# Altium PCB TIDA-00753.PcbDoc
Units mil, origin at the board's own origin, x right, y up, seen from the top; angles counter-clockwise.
Board outline 3149.61 x 1968.5 mil, 2 copper layers (Top Layer, Bottom Layer), stack 62 mil thick; 92 components, 41 nets, 183 pads, 103 vias.
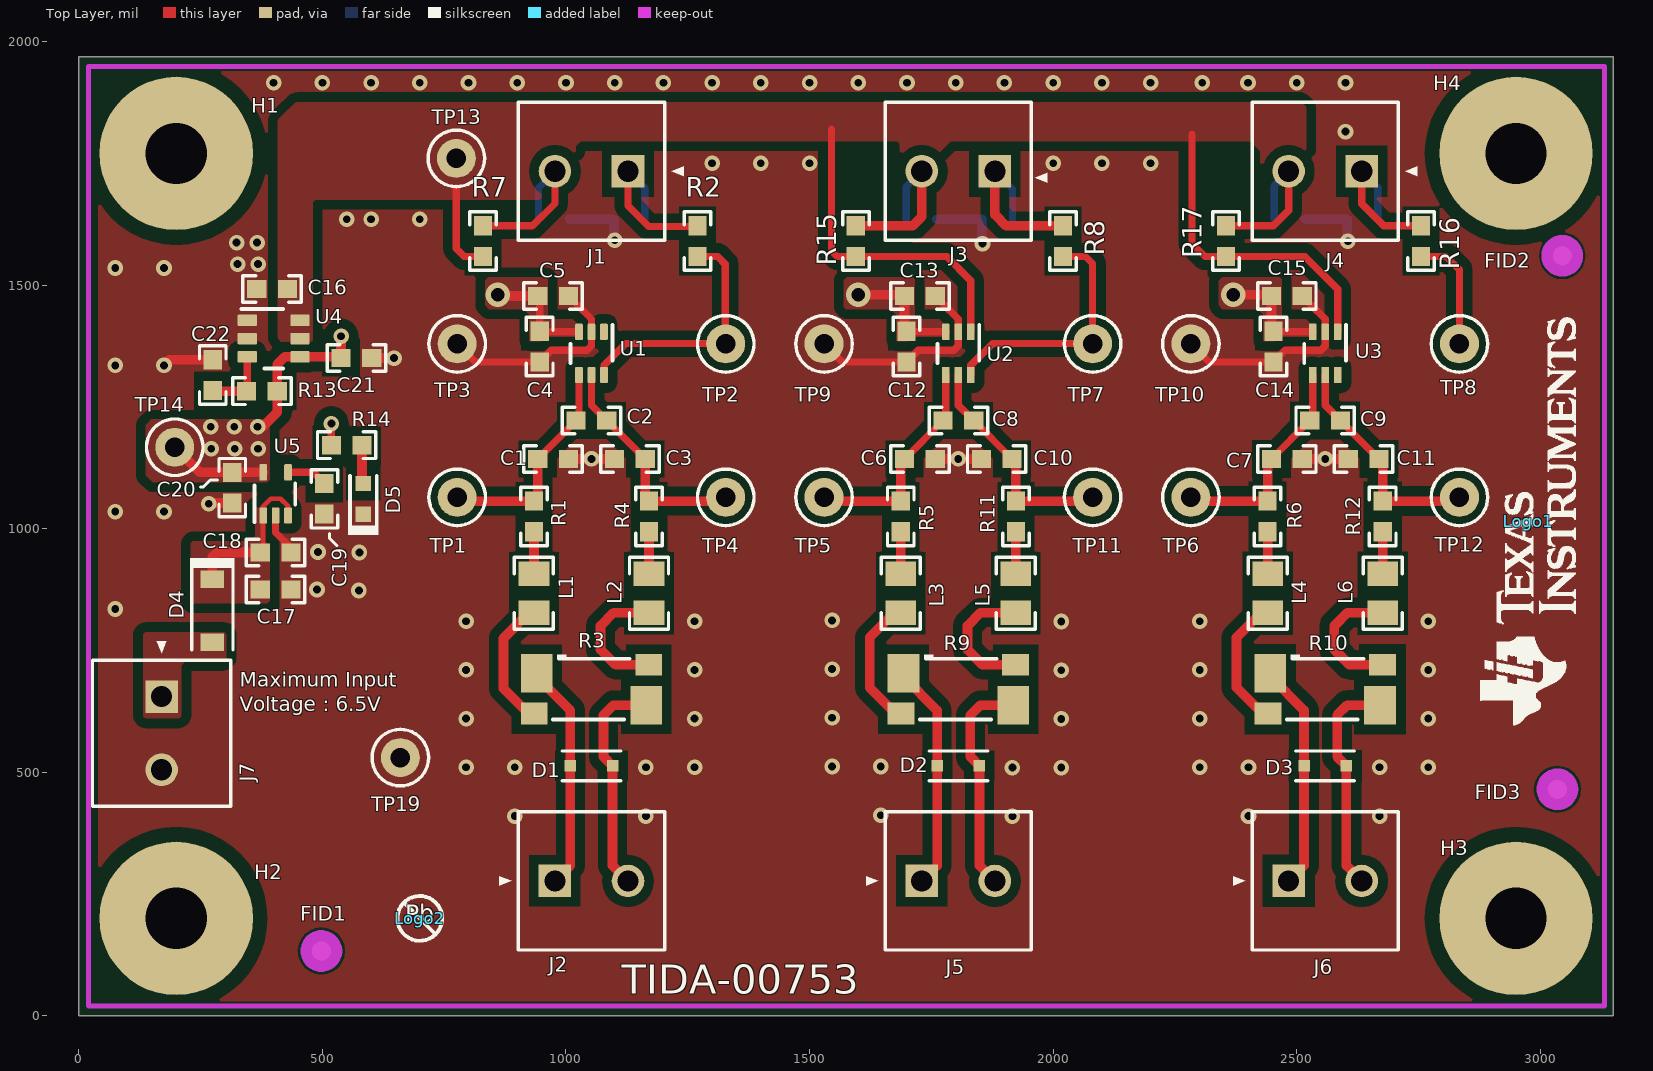
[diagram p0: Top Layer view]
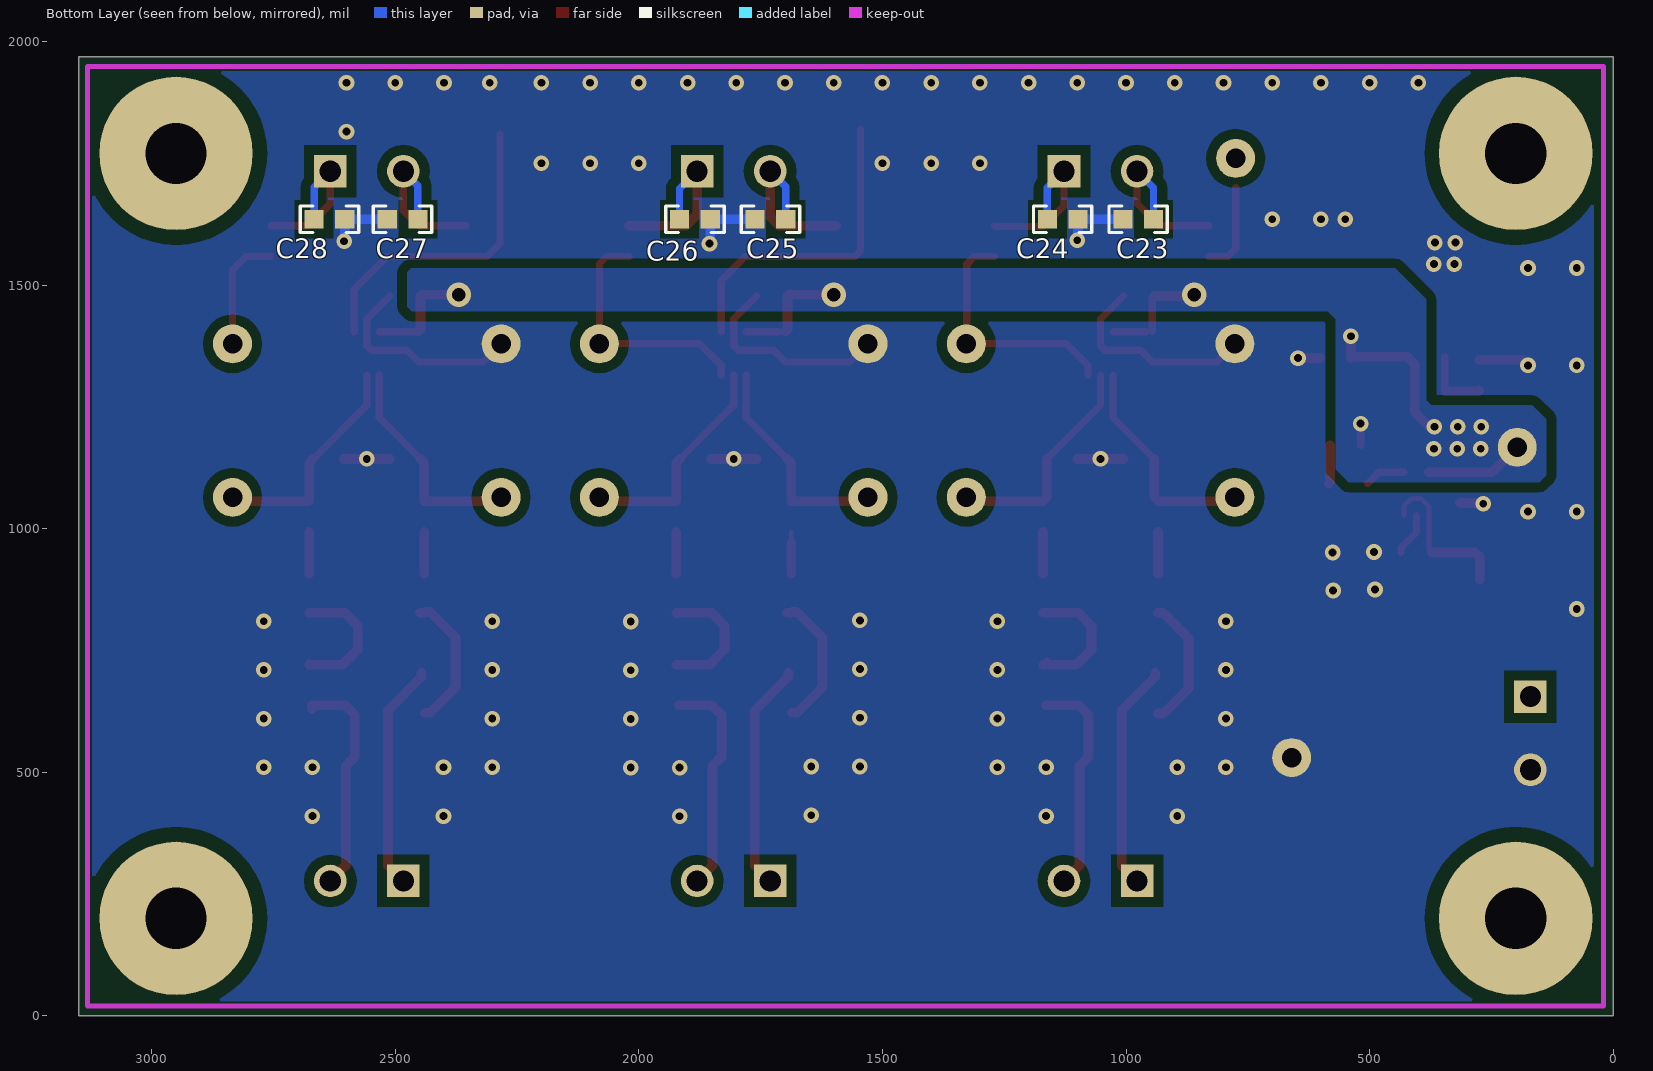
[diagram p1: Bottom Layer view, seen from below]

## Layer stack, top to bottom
Top Solder: solder mask 0.4, Solder Resist, Dk 3.5
Top Layer: signal copper 1.4
Dielectric1: core 59.2, FR-4, Dk 4.8
Bottom Layer: signal copper 1.4
Bottom Solder: solder mask 0.4, Solder Resist, Dk 3.5

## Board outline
0,0 0,1968.5 3149.61,1968.5 3149.61,0

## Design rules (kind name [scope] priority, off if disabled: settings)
AcuteAngle [All] p1: minimum=4.50000000000000E+0001 checktracksonly=FALSE
AssemblyTestPointUsage [All] p1: valid=2
Clearance Clearance_keepout [InPolygon vs IsKeepOut] p1: gap=5
Clearance Clearance_BoardEdge_MountingHoles [OnCopper and InComponentClass('Mounting Holes') vs IsKeepOut] p2: gap=10
Clearance Clearance_HOLES [InPadClass('holes') vs InPoly] p3: gap=30
Clearance "Clearance_Poly to Poly" [InPolygon vs InPolygon] p4: gap=20
Clearance Clearance_Poly [InPolygon] p5: gap=20
Clearance "Clearance_VIA TO VIA" [IsVia vs IsVia] p6: gap=8
Clearance "Clearance_Via to SMD" [IsVia vs IsPad] p7: gap=8
Clearance [All] p8: gap=8
ComponentClearance ComponentClearance_Logo [InComponentClass('Logo')] p1: gap=50 collisioncheckmode=3 verticalgap=10 showdistances=FALSE
ComponentClearance ComponentClearance_ScrewToNut [(HasFootprint('NY PMS 440 0025 PH')) vs (HasFootprint('Keystone_1902C'))] p2: gap=5 collisioncheckmode=3 verticalgap=10 showdistances=FALSE
ComponentClearance ComponentClearance_MountingHoles [InComponentClass('Mounting Holes')] p3: gap=250 collisioncheckmode=3 verticalgap=100000 showdistances=FALSE
ComponentClearance ComponentClearance_SmallPassives [HasFootprint('0201*') or HasFootprint('0402*') or HasFootprint('0508') or HasFootprint('0603*') or HasFootprint('0612') or HasFootprint('0805*') or HasFootprint('0815*') or HasFootprint('0830*') or HasFootprint('1206*') or HasFootprint('1210*') or HasFootprint('1808*') or HasFootprint('1812*') or HasFootprint('1825*') or HasFootprint('2010*') or HasFootprint('2220*') or HasFootprint('2225*') or HasFootprint('2512*') or HasFootprint('2728*') or HasFootprint('3518*') vs HasFootprint('0201*') or HasFootprint('0402*') or HasFootprint('0508') or HasFootprint('0603*') or HasFootprint('0612') or HasFootprint('0805*') or HasFootprint('0815*') or HasFootprint('0830*') or HasFootprint('1206*') or HasFootprint('1210*') or HasFootprint('1808*') or HasFootprint('1812*') or HasFootprint('1825*') or HasFootprint('2010*') or HasFootprint('2220*') or HasFootprint('2225*') or HasFootprint('2512*') or HasFootprint('2728*') or HasFootprint('3518*')] p4: gap=20 collisioncheckmode=3 verticalgap=10 showdistances=FALSE
ComponentClearance ComponentClearance_THtoSMT [IsThruComponent vs IsSMTComponent] p5: gap=100 collisioncheckmode=3 verticalgap=30 showdistances=FALSE
ComponentClearance ComponentClearance_THtoTH [IsThruComponent vs IsThruComponent] p6: gap=118.11 collisioncheckmode=3 verticalgap=30 showdistances=FALSE
ComponentClearance [All] p7: gap=40 collisioncheckmode=3 verticalgap=10 showdistances=FALSE
DiffPairsRouting [All] p1: maxlimit=100 minlimit=10 mostfreqgap=10 toplayer_minwidth=15 toplayer_maxwidth=15 toplayer_prefwidth=15 bottomlayer_minwidth=15 bottomlayer_maxwidth=15 bottomlayer_prefwidth=15 maxuncoupledlength=1000
FabricationTestPointUsage TestPointUsage [All] p1: valid=2 allowmultiple=FALSE
FabricationTestpoint Testpoint [All] p1: side=3 testpointundercomponent=TRUE minsize=40 maxsize=100 preferedsize=60 minholesize=0 maxholesize=40 preferedholesize=32 testpointgrid=1 allowsidetop=TRUE allowsidebottom=TRUE usegrid=TRUE gridtolerance=0.01
FanoutControl Fanout_LCC [IsLCC] p1: bgadir=Out bgaviamode=Centered fanoutstyle=Auto fanoutdirection=Alternating viagrid=1 // Fanout_LCC (Default Rule)
FanoutControl Fanout_BGA [IsBGA] p2: bgadir=Out bgaviamode=Centered fanoutstyle=Auto fanoutdirection=Alternating viagrid=1 // Fanout_BGA (Default Rule)
FanoutControl Fanout_Default [All] p4: bgadir=Out bgaviamode=Centered fanoutstyle=Auto fanoutdirection=Alternating viagrid=1 // Fanout_Default (Default Rule)
FanoutControl Fanout_Small [(CompPinCount < 5)] p5: bgadir=Out bgaviamode=Centered fanoutstyle=Auto fanoutdirection=OutThenIn viagrid=1 // Fanout_Small (Default Rule)
HoleSize [All] p1: absolutevalues=TRUE maxlimit=251 minlimit=7.8 maxpercent=80.000 minpercent=20.000
MatchedLengths [InNetClass('length')] p1: tolerance=50 checknetsindiffpair=TRUE checkdiffpairvsdiffpair=TRUE checkothers=TRUE
MinimumAnnularRing MinimumAnnularRing_ThermalPadVias [IsVia and InAnyComponent] p1: minimumring=5
MinimumAnnularRing [All] p2: minimumring=5
MinimumSolderMaskSliver MinimumSolderMaskSliver_Logo [InComponentClass('Logo') vs InComponentClass('Logo')] p1: minsoldermaskwidth=0.7
MinimumSolderMaskSliver [All] p2: minsoldermaskwidth=3.94
PlaneClearance [All] p1: clearance=16
PlaneConnect [All] p1: planeconnectstyle=Direct reliefexpansion=10 reliefentries=4 reliefconductorwidth=10 reliefairgap=10
PolygonConnect PolygonConnect_TH_PAD [IsThruPin] p1: connectstyle=Direct reliefconductorwidth=20 reliefentries=4 polygonreliefangle="90 Angle" airgapwidth=10
PolygonConnect PolygonConnect_isVia [IsVia] p2: connectstyle=Direct reliefconductorwidth=10 reliefentries=4 polygonreliefangle="90 Angle" airgapwidth=10
PolygonConnect PolygonConnect_SMTPAD [IsSMTPin] p3: connectstyle=Direct reliefconductorwidth=20 reliefentries=4 polygonreliefangle="90 Angle" airgapwidth=10
RoutingVias RoutingVias_PWR [InNetClass('PWR')] p1: holewidth=16 width=30 viastyle="Through Hole" minholewidth=16 minwidth=30 maxholewidth=20 maxwidth=40
RoutingVias [All] p2: holewidth=12 width=24 viastyle="Through Hole" minholewidth=16 minwidth=32 maxholewidth=28 maxwidth=50
RoutingVias ThermalPadVias [InNet('GND_SIGNAL')] p3: holewidth=7.87 width=19.68 viastyle="Through Hole" minholewidth=7.87 minwidth=19.68 maxholewidth=12.99 maxwidth=23.62
SMDToCorner [All] p1: distance=30000
SilkToSilkClearance [All] p1: silktosilkclearance=5
SilkToSolderMaskClearance SilkscreenOverComponentPads [IsPad] p1: minsilkscreentomaskgap=5 clearancetoexposedcopper=TRUE
SolderMaskExpansion [All] p1: expansion=2
UnpouredPolygon [All] p1: allowunpoured=FALSE
ViasUnderSMD [InComponent('U1')] p1: allowed=TRUE
Width Width_PWR [InNetClass('pwr')] p1: maxlimit=100 minlimit=8 preferedwidth=20 minimp=50.000000 maximp=50.000000 favimp=50.000000
Width [All] p2: maxlimit=100 minlimit=10 preferedwidth=10 checkconnectedcopper=TRUE
14 further rules are at their usual default settings.

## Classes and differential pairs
pad class holes: H1-1 H2-1 H3-1 H4-1
component class Amplifier: C1 C2 C3 C4 C5 C6 C7 C8 C9 C10 C11 C12 C13 C14 C15 C16 C17 C18 C19 C20 C21 C22 C23 C24 C25 C26 C27 C28 D1 D2 D3 D4 D5 J1 J2 J3 J4 J5 J6 J7 L1 L2 L3 L4 L5 L6 R1 R2 R3 R4 R5 R6 R7 R8 R9 R10 R11 R12 R13 R14 R15 R16 R17 TP1 TP2 TP3 TP4 TP5 TP6 TP7 TP8 TP9 TP10 TP11 TP12 TP13 TP14 TP19 U1 U2 U3 U4 U5
component class TID_Hardware: FID1 FID2 FID3 H1 H2 H3 H4 Logo1 Logo2
component class FiducialMark: FID1 FID2 FID3
component class "Mounting Holes": H1 H2 H3 H4
component class Logo: Logo1

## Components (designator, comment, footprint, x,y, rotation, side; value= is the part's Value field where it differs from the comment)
C1 "C1608X5R1C105K" 0603 973.62,1142.99 r0 top
C2 "GRM188R60J106ME47D" 0603 1052.36,1221.73 r0 top
C3 "C1608X5R1C105K" 0603 1131.1,1142.99 r0 top
C4 "C1608X5R1C105K" 0603 946.06,1373.53 r270 top
C5 "CGA3E2X8R1E104K080AA" 0603 973.62,1477.64 r0 top
C6 "C1608X5R1C105K" 0603 1726.61,1142.99 r0 top
C7 "C1608X5R1C105K" 0603 2479.61,1142.99 r0 top
C8 "GRM188R60J106ME47D" 0603 1805.35,1221.73 r0 top
C9 "GRM188R60J106ME47D" 0603 2558.35,1221.73 r0 top
C10 "C1608X5R1C105K" 0603 1884.09,1142.99 r0 top
C11 "C1608X5R1C105K" 0603 2637.09,1142.99 r0 top
C12 "C1608X5R1C105K" 0603 1699.06,1373.53 r270 top
C13 "CGA3E2X8R1E104K080AA" 0603 1726.61,1477.64 r0 top
C14 "C1608X5R1C105K" 0603 2452.05,1373.53 r270 top
C15 "CGA3E2X8R1E104K080AA" 0603 2479.61,1477.64 r0 top
C16 "CGA3E2X8R1E104K080AA" 0603 397,1492 r180 top
C17 "C1608X5R1C105K" 0603 404,875.2 r0 top
C18 "CGA3E2X8R1E104K080AA" 0603 404,951.2 r0 top
C19 "C0603X102K5RACTU" 0603 504,1061.2 r270 top
C20 "C1608X5R1C105K" 0603 315,1084 r270 top
C21 "C0603C474K4RACTU" 0603 570,1350 r0 top
C22 "CGA3E2X8R1E104K080AA" 0603 275,1315 r90 top
C23 "GRM188R60J106ME47D" 0603 975,1635.07 r0 bottom
C24 "GRM188R60J106ME47D" 0603 1130,1635 r180 bottom
C25 "GRM188R60J106ME47D" 0603 1730,1635 r0 bottom
C26 "GRM188R60J106ME47D" 0603 1885,1635 r180 bottom
C27 "GRM188R60J106ME47D" 0603 2485,1635 r0 bottom
C28 "GRM188R60J106ME47D" 0603 2635,1634.93 r180 bottom
D1 "CDSOD323-T03SC" SOD-323-Bi 1052.36,513.07 r180 top
D2 "CDSOD323-T03SC" SOD-323-Bi 1805.35,513.07 r180 top
D3 "CDSOD323-T03SC" SOD-323-Bi 2558.35,513.07 r180 top
D4 "BAT41ZFILM" SOD-123 274,831.2 r270 top
D5 "150060GS75000" WL-SMCW_GREEN 584,1061.2 r90 top
FID1 "Fiducial" Fiducial10-20 498,133 r0 top
FID2 "Fiducial" Fiducial10-20 3045,1560 r0 top
FID3 "Fiducial" Fiducial10-20 3035,465 r0 top
H1 "NY PMS 440 0025 PH" "NY PMS 440 0025 PH" 200,1770 r0 top
H2 "NY PMS 440 0025 PH" "NY PMS 440 0025 PH" 200,200 r0 top
H3 "NY PMS 440 0025 PH" "NY PMS 440 0025 PH" 2950,200 r0 top
H4 "NY PMS 440 0025 PH" "NY PMS 440 0025 PH" 2950,1770 r0 top
J1 "1727010" PhoenixConact_1727010 1052.36,1733.54 r180 top
J2 "1727010" PhoenixConact_1727010 1052.36,276.85 r0 top
J3 "1727010" PhoenixConact_1727010 1805.35,1733.54 r180 top
J4 "1727010" PhoenixConact_1727010 2558.35,1733.54 r180 top
J5 "1727010" PhoenixConact_1727010 1805.35,276.85 r0 top
J6 "1727010" PhoenixConact_1727010 2558.35,276.85 r0 top
J7 "1727010" PhoenixConact_1727010 170,580 r270 top
L1 "FBMJ2125HM210NT" 0805_HV 934.25,867.4 r90 top
L2 "FBMJ2125HM210NT" 0805_HV 1170.47,867.4 r90 top
L3 "FBMJ2125HM210NT" 0805_HV 1687.24,867.4 r90 top
L4 "FBMJ2125HM210NT" 0805_HV 2440.24,867.4 r90 top
L5 "FBMJ2125HM210NT" 0805_HV 1923.46,867.4 r90 top
L6 "FBMJ2125HM210NT" 0805_HV 2676.46,867.4 r90 top
Logo1 "Texas Instruments" TI_Stacked_Overlay_Small 2975,1015 r90 top
Logo2 "Pb-Free Symbol" Pb-Free_Overlay_Small 700,200 r0 top
R1 "RT0603DRE071R01L" 0603 934.25,1024.88 r90 top
R2 "RC0603FR-0710RL" 0603 1270,1590 r90 top
R3 "Y14870R10000B9W" CSM2512_T3 1052.36,670.55 r0 top
R4 "RT0603DRE071R01L" 0603 1170.47,1024.88 r90 top
R5 "RT0603DRE071R01L" 0603 1687.24,1024.88 r90 top
R6 "RT0603DRE071R01L" 0603 2440.24,1024.88 r90 top
R7 "RC0603FR-0710RL" 0603 830,1590 r90 top
R8 "RC0603FR-0710RL" 0603 2020,1590 r90 top
R9 "Y14870R10000B9W" CSM2512_T3 1805.35,670.55 r0 top
R10 "Y14870R10000B9W" CSM2512_T3 2558.35,670.55 r0 top
R11 "RT0603DRE071R01L" 0603 1923.46,1024.88 r90 top
R12 "RT0603DRE071R01L" 0603 2676.46,1024.88 r90 top
R13 "CRCW0603150KFKEA" 0603 376,1282 r0 top
R14 "RC0603FR-07390RL" 0603 550,1171.2 r180 top
R15 "RC0603FR-0710RL" 0603 1595,1590 r90 top
R16 "RC0603FR-0710RL" 0603 2755,1590 r90 top
R17 "RC0603FR-0710RL" 0603 2355,1590 r90 top
TP1 "5000" Keystone5000 776.77,1064.25 r90 top
TP2 "5002" Keystone5002 1327.95,1379.21 r90 top
TP3 "5001" Keystone5001 776.77,1379.21 r90 top
TP4 "5004" Keystone5004 1327.95,1064.25 r270 top
TP5 "5000" Keystone5000 1529.76,1064.25 r90 top
TP6 "5000" Keystone5000 2282.76,1064.25 r90 top
TP7 "5002" Keystone5002 2080.94,1379.21 r90 top
TP8 "5002" Keystone5002 2833.94,1379.21 r90 top
TP9 "5001" Keystone5001 1529.76,1379.21 r90 top
TP10 "5001" Keystone5001 2282.76,1379.21 r90 top
TP11 "5004" Keystone5004 2080.94,1064.25 r90 top
TP12 "5004" Keystone5004 2833.94,1064.25 r90 top
TP13 "5002" Keystone5002 775,1760 r90 top
TP14 "5002" Keystone5002 197,1167 r90 top
TP19 "5001" Keystone5001 660,530 r90 top
U1 "INA199A1DCKR" DCK0006A_N 1052.36,1359.53 r270 top
U2 "INA199A1DCKR" DCK0006A_N 1805.35,1359.53 r270 top
U3 "INA199A1DCKR" DCK0006A_N 2558.35,1359.53 r270 top
U4 "REF3212AIDBVR" DBV0006A_N 400,1390 r0 top
U5 "TPS71733DCKR" DCK0005A_N 404,1071.2 r90 top

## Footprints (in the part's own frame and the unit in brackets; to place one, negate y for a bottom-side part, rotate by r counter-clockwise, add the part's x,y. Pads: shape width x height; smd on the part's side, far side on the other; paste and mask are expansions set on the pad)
0603 [mm] "0603 from SM-752 data"
  rect 1x0.95 smd: 1(-0.8,0) 2(0.8,0)
  silkscreen extent -1.52,-0.69 1.52,0.69, body extent -0.87,-0.47 0.87,0.47, height 1
0805_HV [mil] "0805 with 30mil clearance between pads"
  rect 50x63 smd: 1(-40,0) 2(40,0)
  silkscreen extent -74,-40 74,40, body extent -43,-29 43,29, height 57
CSM2512_T3 [mm] "SMD, 4-Leads, Body 6.35x3.175mm"
  rect 1.65x2.01 smd: 1(-2.855,0.835) 2(2.855,-0.835)
  rect 1.39x1.14 smd: 3(-2.985,-1.27) 4(2.985,1.27)
  silkscreen extent -2,-1.59 2,1.8, body extent -3.17,-1.59 3.18,1.59, height 0.7
DBV0006A_N [mm] "SOT23, 6-Leads, Body 2.9x1.6mm, Pitch 0.95mm, Lead Span 2.8mm, IPC Medium Density"
  rrect17% 1x0.6 smd: 1(-1.375,0.95) 2(-1.375,0) 3(-1.375,-0.95) 4(1.375,-0.95) 5(1.375,0) 6(1.375,0.95)
  silkscreen extent -1.68,-1.55 0.5,1.55, body extent -1.42,-1.46 1.42,1.46, height 1.12
DCK0005A_N [mm] "SOT353, 5-Leads, Body 2x1.3mm, Pitch 0.65mm, Lead Span 2.1mm, IPC Medium Density"
  rrect25% 0.85x0.4 smd: 1(-1.125,0.65) 2(-1.125,0) 3(-1.125,-0.65) 4(1.125,-0.65) 5(1.125,0.65)
  silkscreen extent -1.48,-1.02 0.55,1.1, body extent -1.14,-1 1.14,1, height 0.95
DCK0006A_N [mm] "SOT23, 6-Leads, Body 2x1.3mm, Pitch 0.65mm, Lead Span 2.1mm, IPC Medium Density"
  rrect25% 0.85x0.4 smd: 1(-1.125,0.65) 2(-1.125,0) 3(-1.125,-0.65) 4(1.125,-0.65) 5(1.125,0) 6(1.125,0.65)
  silkscreen extent -1.5,-1.09 0.51,1.09, body extent -1.14,-1 1.14,1, height 0.95
Fiducial10-20 [mm]
  round 1 smd mask+0.5: 1(0,0)
  Top Layer keep-out circle w1.178: c0,0 r0.5
Keystone5000 [mil] "For Keystone 500x miniature loop terminals"
  round 80 hole 40: 1(0,0)
  silkscreen extent -58,-58 58,58, body extent -49,-49 49,49, height 182
Keystone5001 [mil] "For Keystone 500x miniature loop terminals"
  round 80 hole 40: 1(0,0)
  silkscreen extent -58,-58 58,58, body extent -49,-49 49,49, height 182
Keystone5002 [mil] "For Keystone 500x miniature loop terminals"
  round 80 hole 40: 1(0,0)
  silkscreen extent -58,-58 58,58, body extent -49,-49 49,49, height 182
Keystone5004 [mil] "For Keystone 500x miniature loop terminals"
  round 80 hole 40: 1(0,0)
  silkscreen extent -58,-58 58,58, body extent -49,-49 49,49, height 182
"NY PMS 440 0025 PH" [mm] "4-40 nylon screw and mounting hole"
  round 8 hole 3.2: 1(0,0)
  body extent -3.3,-3.3 3.3,3.3, height 2.69
Pb-Free_Overlay_Small [mil]
  silkscreen extent -46,-46 46,46
PhoenixConact_1727010 [mm]
  rect 1.7x1.7 hole 1.1: 1(-1.905,0)
  round 1.7 hole 1.1: 2(1.905,0)
  silkscreen extent -4.8,-3.6 3.81,3.6, body extent -3.81,-3.6 3.81,3.7, height 8.52
SOD-123 [mm] "On Semi recommended land pattern"
  rect 0.915x1.22 smd: 1(-1.637,0) 2(1.637,0)
  silkscreen extent -2.74,-1.17 2.03,1.17, body extent -1.93,-0.9 1.93,0.9, height 1.35
SOD-323-Bi [mm] "SOD323, 2-Leads, Body 1.9x1.45mm, No Polarity Mark"
  rect 0.6x0.6 smd paste-0.05: 1(-1.1,0) 2(1.1,0)
  silkscreen extent -1.53,-0.77 1.53,0.77, body extent -1.27,-0.65 1.27,0.65, height 1.02
TI_Stacked_Overlay_Small [mil]
  silkscreen extent -418,-98 418,98
WL-SMCW_GREEN [mm] "WURTH"
  rect 0.8x0.8 smd: 1(-0.8,0) 2(0.8,0)
  silkscreen extent -1.9,-0.8 1.2,0.8, body extent -0.85,-0.45 0.85,0.45, height 0.8

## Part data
C1 C3 C4 C6 C7 C10 C11 C12 C14 C17 C20: "CAP, CERM, 1 µF, 16 V, +/- 10%, X5R, 0603"
C2 C8 C9 C23 C24 C25 C26 C27 C28: "CAP, CERM, 10 µF, 6.3 V, +/- 20%, X5R, 0603"
C5 C13 C15 C16 C18 C22: "CAP, CERM, 0.1 µF, 25 V, +/- 10%, X8R, AEC-Q200 Grade 0, 0603"
C19: "CAP, CERM, 1000 pF, 50 V, +/- 10%, X7R, 0603"
C21: "CAP, CERM, 0.47 µF, 16 V, +/- 10%, X7R, 0603"
D1 D2 D3: "Diode, TVS, Bi, 3.3 V, 400 W, SOD323, 2-Leads, Body 1.9x1.45mm, No Polarity Mark"
D4: "Diode, Schottky, 100 V, 0.2 A, SOD-123"
D5: "LED, Green, SMD"
FID1 FID2 FID3: "Fiducial mark.  There is nothing to buy or mount."
H1 H2 H3 H4: "Machine Screw, Round, #4-40 x 1/4, Nylon, Philips panhead"
J1 J2 J3 J4 J5 J6 J7: "Conn Term Block, 2POS, 3.81mm, TH"
L1 L2 L3 L4 L5 L6: "Ferrite Bead, 21 ohm @ 100 MHz, 6 A, 0805"
Logo1: library part TI_Logo, "Texas Instrument Corporate Signature"
Logo2: library part Pb-Free
R1 R4 R5 R6 R11 R12: "RES, 1.01, 0.5%, 0.1 W, 0603"
R2 R7 R8 R15 R16 R17: "RES, 10.0, 1%, 0.1 W, 0603"
R3 R9 R10: "RES, 0.1, 0.1%, 1 W, 6.35x3.175mm"
R13: "RES, 150 k, 1%, 0.1 W, 0603"
R14: "RES, 390, 1%, 0.1 W, 0603"
TP1 TP5 TP6: "Test Point, Miniature, Red, TH"
TP2 TP7 TP8 TP13 TP14: "Test Point, Miniature, White, TH"
TP3 TP9 TP10 TP19: "Test Point, Miniature, Black, TH"
TP4 TP11 TP12: "Test Point, Miniature, Yellow, TH"
U1 U2 U3: "Voltage Output, High or Low Side Measurement, Bi-Directional Zerø-Drift Series Current-Shunt Monitor, DCK0006A"
U4: "1.25 V, 4 ppm / degC, 100 uA Series (Bandgap) Voltage Reference, -40 to 125 degC, 6-pin SOT-23 (DBV), Green (RoHS & no Sb/Br)"
U5: "Single Output High PSRR LDO, 150 mA, Fixed 3.3 V Output, 2.5 to 6.5 V Input, with Low IQ, 5-pin SC70 (DCK), -40 to 85 degC, Green (RoHS & no Sb/Br)"

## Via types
v1: diameter 32, hole 16, Top Layer to Bottom Layer, 100 vias
v2: diameter 50, hole 28, Top Layer to Bottom Layer, 3 vias

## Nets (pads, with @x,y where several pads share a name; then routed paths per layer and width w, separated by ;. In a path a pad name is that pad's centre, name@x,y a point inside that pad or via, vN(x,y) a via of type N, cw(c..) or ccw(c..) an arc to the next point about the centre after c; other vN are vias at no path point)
+3.3V: C4.1 C5.1 C12.1 C13.1 C14.1 C15.1 C20.1 C21.1 R13.2 R14.2 TP14.1 U1.3 U2.3 U3.3 U4.4 U5.5 | length 1276.1
  Top Layer w10: v2(860,1480) v2@862.36,1477.64 ; C5.1 945.57,1477.64 C5.1
  Top Layer w15: R14.2 v1(518.5,1215.5) ; C5.1 946.06,1473.7 C4.1 ; C4.1@958.86,1403.82 U1.3 ; C12.1@1711.85,1403.82 U2.3 ; C14.1 2453.25,1403.82 U3.3
  Top Layer w20: TP14.1 248.5,1115.5 C20.1 U5.5 ; v1(367,1209) 377,1209 407.5,1239.5 R13.2 407.5,1337.5 422.6,1352.6 U4.4 C21.1@535.91,1352.6 ; C21.1 v1(538.5,1395) ; v2@862.36,1477.64 C5.1 ; v2(1600,1480) C13.1@1692.76,1480 ; C13.1 1695.12,1408.96 C12.1 ; v2(2370,1480) C15.1@2445.75,1480 ; C15.1 2448.11,1408.96 C14.1
  other v1: 272,1164 320,1164 368,1164 271,1209 319,1209
GND: C1.2 C3.1 C4.2 C5.2 C6.2 C7.2 C10.1 C11.1 C12.2 C13.2 C14.2 C15.2 C16.2 C17.2 C18.2 C19.2 C20.2 C21.2 C22.2 C23.2 C24.2 C25.2 C26.2 C27.2 C28.2 D5.1 J7.2 TP3.1 TP9.1 TP10.1 TP19.1 U1.2 U2.2 U3.2 U4.1 U4.2 U5.2 | length 2262.1
  Top Layer w15: U5.2 404,992 435.5,960.5 C18.2 ; TP3.1 813.95,1342.03 C4.2 970.03,1366 1043,1366 1052.36,1375.36 U1.2 1052.36,1430.39 C5.2 ; TP9.1 1566.94,1342.03 C12.2 1723.02,1366 1795.99,1366 1805.35,1375.36 U2.2 1805.35,1430.39 C13.2 ; TP10.1 2319.94,1342.03 C14.2 2476.02,1366 2548.98,1366 2558.35,1375.36 U3.2 2558.35,1430.39 C15.2
  Top Layer w20: v1(175,1335) 186.5,1346.5 C22.2 ; v1(267,1051) 268.5,1052.5 C20.2 ; C21.2 v1(647,1350) ; C1.2 v1(1052.36,1142.99) C3.1 ; C6.2 C10.1 ; C7.2 C11.1
  Bottom Layer w20: C23.2 1098.44,1635.07 C24.2 1098.5,1593.31 v1(1100,1591.81) ; C25.2 C26.2 1853.5,1586.5 v1(1855,1585) ; C27.2 2603.44,1635 C28.2 2603.5,1591.5 v1(2605,1590)
  other v1: 1916.42,409.41 895,410 1164.02,410 2400.98,410 2670,410 1646.34,411.65 1916.42,509.41 2016.42,509.41 795,510 895,510 1164.02,510 1264.02,510 2300.98,510 2400.98,510 2670,510 2770,510 1546.34,511.65 1646.34,511.65 2016.42,609.41 795,610 1264.02,610 2300.98,610 2770,610 1546.34,611.65 2016.42,709.41 795,710 1264.02,710 2300.98,710 2770,710 1546.34,711.65 2016.42,809.41 795,810 1264.02,810 2300.98,810 2770,810 1546.34,811.65 75,835 575,873 489,875 576,951 491,952 75,1035 175,1035 1805.35,1142.99 2558.35,1142.99 75,1335 75,1535 175,1535 326,1543 368,1543 324,1587 366,1587 550,1635 600,1635 700,1635 1300,1750 1400,1750 1500,1750 2000,1750 2100,1750 2200,1750 2600,1815 400,1915 500,1915 600,1915 700,1915 800,1915 900,1915 1000,1915 1100,1915 1200,1915 1300,1915 1400,1915 1500,1915 1600,1915 1700,1915 1800,1915 1900,1915 2000,1915 2100,1915 2200,1915 2305.98,1915 2400,1915 2500,1915 2600,1915
NetC1_1: C1.1 C2.1 R1.2 TP1.1 U1.4 | length 457.9
  Top Layer w10: TP1.1 TP1.1@784.65,1056.38 ; R1.2 R1.2@942.13,1064.25
  Top Layer w15: C1.1 C2.1 1026.77,1227.64 U1.4
  Top Layer w20: TP1.1@784.65,1056.38 R1.2 ; R1.2@942.13,1064.25 C1.1
NetC2_2: C2.2 C3.2 R4.2 TP4.1 U1.5 | length 468.5
  Top Layer w10: R4.2@1162.6,1064.25 R4.2 ; TP4.1@1320.08,1056.38 TP4.1
  Top Layer w15: U1.5 1052.36,1253.23 C2.2 C3.2
  Top Layer w20: R4.2@1162.6,1064.25 C3.2 ; R4.2 TP4.1@1320.08,1056.38
NetC6_1: C6.1 C8.1 R5.2 TP5.1 U2.4 | length 457.9
  Top Layer w15: C6.1 C8.1 1779.76,1227.64 U2.4
  Top Layer w20: TP5.1 1537.64,1056.38 R5.2 1687.24,1135.12 C6.1
NetC7_1: C7.1 C9.1 R6.2 TP6.1 U3.4 | length 457.9
  Top Layer w15: C7.1 C9.1 2532.76,1227.64 U3.4
  Top Layer w20: TP6.1 2290.63,1056.38 R6.2 2440.24,1135.12 C7.1
NetC8_2: C8.2 C10.2 R11.2 TP11.1 U2.5 | length 468.5
  Top Layer w15: U2.5 1805.35,1253.23 C8.2 C10.2
  Top Layer w20: C10.2 1923.46,1135.12 R11.2 2073.07,1056.38 TP11.1
NetC9_2: C9.2 C11.2 R12.2 TP12.1 U3.5 | length 468.5
  Top Layer w15: U3.5 2558.35,1253.23 C11.2
  Top Layer w20: C11.2 2676.46,1135.12 R12.2 2826.06,1056.38 TP12.1
NetC17_1: C17.1 C18.1 D4.1 U5.1 U5.3 | length 327.8
  Top Layer w10: C18.1 378.41,957.11 U5.1 378.41,1045.61 394,1061.2 414,1061.2 429.59,1045.61 U5.3
  Top Layer w20: D4.1 274,941.2 284,951.2 C18.1
NetC19_1: C19.1 U5.4 | length 83.9
  Top Layer w15: U5.4 481.2,1115.49 C19.1
NetC22_1: C22.1 R13.1 U4.3 | length 141.3
  Top Layer w15: R13.1 345.87,1283.36 U4.3
  Top Layer w20: C22.1 276.5,1282 R13.1
NetC23_1: C23.1 J1.2 R7.2 | length 345
  Top Layer w15: R7.2 931.5,1621.5 977.36,1667.36 J1.2
  Bottom Layer w15: C23.1 943.5,1699.68 J1.2
NetC24_1: C24.1 J1.1 R2.2 | length 344.5
  Top Layer w15: J1.1 1127.36,1662.64 1170,1620 1268.5,1620 R2.2
  Bottom Layer w15: J1.1 1161.5,1699.41 C24.1
NetC25_1: C25.1 J3.2 R15.2 | length 348.1
  Top Layer w20: R15.2 1711.5,1621.5 1730.35,1640.35 J3.2
  Bottom Layer w15: C25.1 1698.5,1701.69 J3.2
NetC26_1: C26.1 J3.1 R8.2 | length 351.6
  Top Layer w20: J3.1 1880.35,1644.65 1903.5,1621.5 R8.2
  Bottom Layer w15: J3.1 1916.5,1697.4 C26.1
NetC27_1: C27.1 J4.2 R17.2 | length 332.6
  Top Layer w15: R17.2 2451.5,1621.5 2483.35,1653.35 J4.2
  Bottom Layer w15: C27.1 2453.5,1703.7 J4.2
NetC28_1: C28.1 J4.1 R16.2 | length 319.6
  Top Layer w15: J4.1 2633.35,1666.65 2678.5,1621.5 R16.2
  Bottom Layer w15: J4.1 2666.5,1700.39 C28.1
NetD1_1: D1.1 J2.2 R3.2 | length 457.3
  Top Layer w20: J2.2 1095.67,308.54 D1.1 1077,531.74 1077,617 1097.68,637.68 R3.2
NetD1_2: D1.2 J2.1 R3.1 | length 468.3
  Top Layer w20: R3.1 939.96,696.04 1009.06,626.95 D1.2 1009.06,308.54 J2.1
NetD2_1: D2.1 J5.2 R9.2 | length 457.3
  Top Layer w20: J5.2 1848.66,308.54 D2.1 1829.99,531.74 1829.99,617 1850.67,637.68 R9.2
NetD2_2: D2.2 J5.1 R9.1 | length 468.3
  Top Layer w20: R9.1 1692.95,696.04 1762.05,626.95 D2.2 1762.05,308.54 J5.1
NetD3_1: D3.1 J6.2 R10.2 | length 465.3
  Top Layer w20: J6.2 2601.65,308.54 D3.1 2582.98,531.74 2582.98,617 2603.66,637.68 R10.2 R10.2@2670.75,629.75
NetD3_2: D3.2 J6.1 R10.1 | length 475.3
  Top Layer w10: D3.2 D3.2@2520,518.03
  Top Layer w20: R10.1 2445.94,696.04 2515.04,626.95 D3.2 2515.04,308.54 J6.1
NetD4_2: D4.2 J7.1
NetD5_2: D5.2 R14.1 | length 79.5
  Top Layer w20: R14.1 581.5,1095.2 D5.2
NetL1_2: L1.2 R1.1 | length 86
  Top Layer w20: L1.2 R1.1
NetL2_2: L2.2 R4.1 | length 86
  Top Layer w20: L2.2 R4.1
NetL3_1: L3.1 R9.3 | length 280.5
  Top Layer w20: L3.1@1685.59,829.06 1675.74,829.06 1623.34,776.65 1623.34,673.65 1674.79,622.2 R9.3@1686.18,622.2 ; L3.1 L3.1@1696.61,827.4
NetL3_2: L3.2 R5.1 | length 86
  Top Layer w10: 1687.24,970.7 R5.1
  Top Layer w20: L3.2 1687.24,970.7
NetL4_1: L4.1 R10.3 | length 280.5
  Top Layer w20: L4.1@2438.58,829.06 2428.73,829.06 2376.33,776.65 2376.33,673.65 2427.78,622.2 R10.3@2439.17,622.2 ; L4.1 L4.1@2449.6,827.4
NetL4_2: L4.2 R6.1 | length 86
  Top Layer w20: L4.2 R6.1
NetL5_1: L5.1 R9.4 | length 272.1
  Top Layer w20: R9.4 1854.99,720.55 1823.99,751.55 1823.99,800.4 1850.99,827.4 L5.1 L5.1@1922.87,826.81
NetL5_2: L5.2 R11.1 | length 86
  Top Layer w20: L5.2 R11.1
NetL6_1: L6.1 R10.4 | length 272.1
  Top Layer w20: R10.4@2676.46,721.14 R10.4 2607.98,720.55 2576.98,751.55 2576.98,800.4 2603.98,827.4 L6.1
NetL6_2: L6.2 R12.1 | length 86
  Top Layer w20: L6.2 R12.1
VBIAS: C16.1 R7.1 R15.1 R17.1 TP13.1 U1.1 U2.1 U3.1 U4.5 U4.6 | length 1503.1
  Top Layer w15: 775,1699.71 775,1575 791.5,1558.5 R7.1 ; 1545,1820 1545,1570 1556.5,1558.5 R15.1 1781.5,1558.5 1830.94,1509.06 U2.1 ; 2285,1810 2285,1585 2311.5,1558.5 R17.1 2516.5,1558.5 2583.94,1491.06 U3.1
VIN_1: R2.1 TP2.1 U1.6 | length 514.4
  Top Layer w15: U1.6 1077.95,1335.13 1122.72,1379.89 1327.27,1379.89 1327.27,1542.73 1311.5,1558.5 R2.1
VIN_1+: L1.1 R3.3 | length 273.4
  Top Layer w10: R3.3 R3.3@936.5,618.9
  Top Layer w20: L1.1 924.4,827.4 872,775 872,672 923.45,620.55 R3.3
VIN_1-: L2.1 R3.4 | length 281.8
  Top Layer w15: R3.4@1162.38,728.05 R3.4
  Top Layer w20: R3.4 1102,720.55 1071,751.55 1071,800.4 1098,827.4 L2.1
VIN_2: R8.1 TP7.1 U2.6 | length 520.5
  Top Layer w15: U2.6 1830.94,1335.13 1875.71,1379.89 2080.26,1379.89 TP7.1 2080.94,1544.06 2066.5,1558.5 R8.1
VIN_3: R16.1 TP8.1 U3.6 | length 242.2
  Top Layer w15: R16.1 2806.5,1558.5 2833.94,1531.06 TP8.1
pads on no net: FID1.1 FID2.1 FID3.1 H1.1 H2.1 H3.1 H4.1

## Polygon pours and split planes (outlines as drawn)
+3.3V on Top Layer "Top Layer-No Net 1" (solid, remove dead copper, pour order 15): 1034,1419 1034,1387.07 1031.18,1384.25 926.75,1384.25 925,1386 925,1439.08 913.64,1450.44 841.56,1450.44 834,1458 834,1509 841,1516 959,1516 963,1512 963,1433 966,1430 1029,1430 1034,1425
+3.3V on Top Layer "Top Layer-No Net 1" (solid, remove dead copper, pour order 14): 1786.99,1419 1786.99,1387.07 1784.17,1384.25 1679.74,1384.25 1677.99,1386 1677.99,1439.08 1666.63,1450.44 1574.56,1450.44 1570,1455 1570,1510 1576,1516 1711.99,1516 1715.99,1512 1715.99,1433 1718.99,1430 1781.99,1430 1786.99,1425
+3.3V on Top Layer "Top Layer-No Net 1" (solid, remove dead copper, pour order 13): 2539.98,1419 2539.98,1387.07 2537.17,1384.25 2432.73,1384.25 2430.98,1386 2430.98,1439.08 2419.62,1450.44 2347.55,1450.44 2339.98,1458 2339.98,1509 2346.98,1516 2464.98,1516 2468.98,1512 2468.98,1433 2471.98,1430 2534.98,1430 2539.98,1425
NetD4_2 on Top Layer "Top Layer-No Net 1" (solid, remove dead copper, pour order 16): 297,787 136,787 132,783 132,615 136,611 206,611 210,615 210,719 220,729 298,729 303,734 303,783 299,787
NetC17_1 on Top Layer "Top Layer-No Net 1" (solid, remove dead copper, pour order 17): 362,1043.32 382.42,1043.64 382.86,1043.2 382.86,979.14 392,970 392,851.66 387,846.66 233.34,846.66 230,850 230,970 234,974 352,974 362,984
GND on Top Layer "Top Layer-No Net 1" (solid, remove dead copper, pour order 18): 414,970 414,849 419,844 621,844 625,848 625,1046 620,1051 484,1051 475.46,1042 475.46,990.18 465.02,979.74 421.74,979.74 414,972
GND on Top Layer "Top Layer-No Net 1" (solid, remove dead copper, pour order 19): 383,1388 317,1388 312,1393 312,1608 314,1610 381,1610 386,1605 386,1391
+3.3V on Top Layer "Top Layer-No Net 1" (solid, remove dead copper, pour order 21): 300,1095 387,1095 392,1100 392,1214 382,1224 149,1224 137,1212 137,1110 152,1095
VBIAS on Top Layer "Top Layer-No Net 1" (solid, remove dead copper, pour order 24): 1695,1700 1755,1700 1765,1710 1765,1770 1790,1795 2405,1795 2425,1775 2425,1705 2435,1695 2505,1695 2520,1710 2520,1865 2509.72,1875.28 2408.35,1875.28 445.28,1875.28 408,1838 408,1474 408,1391 415,1384 477.09,1384 480,1386.91 480,1670 485,1675 765,1675 995,1675 1020,1700 1020,1785 1030,1795 1680,1795 1685,1790 1685,1705 1690,1700
GND on Top Layer "Top Layer-No Net 1" (solid, remove dead copper, pour order 23): 40,1945 40,75 95,20 3065,20 3131.61,86.61 3131.61,1868.39 3055,1945
+3.3V on Bottom Layer "Top Layer-No Net 1" (solid, remove dead copper, pour order 20): 2320,1534 2467,1534 2475,1526 2475,1455 2466,1446 586,1446 570,1430 570,1151 570,1122 543,1095 152,1095 137,1110 137,1224 166,1253 374,1253 384,1263 384,1471 447,1534 2299,1534
GND on Bottom Layer "Top Layer-No Net 1" (solid, remove dead copper, pour order 22): 40,1945 40,75 95,20 3065,20 3131.61,86.61 3131.61,1868.39 3055,1945

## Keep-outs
Keep-Out Layer:
  lines w10: 20,20 20,1948.5 3131.61,1948.5 3131.61,20 20,20

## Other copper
Top Layer:
  text ".Layer_Name" at -39.8,-1383.54 h60
Bottom Layer:
  text ".Layer_Name" at -39.8,-1383.54 h60

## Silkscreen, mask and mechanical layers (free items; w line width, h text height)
Top Overlay:
  lines w6: 250,1085 255,1085 270,1100 275,1100 285,1100 ; 515,990 515,980 530,965
  text "Maximum Input" at 330,675 h30
  text "Voltage : 6.5V" at 330,625 h30
  text "TIDA-00753" at 1115,45 h60
  text ".Layer_Name" at -39.8,-1383.54 h60
Bottom Overlay:
  text ".Layer_Name" at -39.8,-1383.54 h60
Top Paste:
  text ".Layer_Name" at -39.8,-1383.54 h60
Bottom Paste:
  text ".Layer_Name" at -39.8,-1383.54 h60
Top Solder:
  text ".Layer_Name" at -39.8,-1383.54 h60
  text ".Layer_Name" at -39.8,-1383.54 h60
Bottom Solder:
  text ".Layer_Name" at -39.8,-1383.54 h60
Drill Guide:
  text ".Layer_Name" at -39.8,-1383.54 h60
M1 Board Outline:
  the board outline again, w10
M2 Board Dimensions:
  rectangle: -617.3,-810.54 -492.3,-685.54
  rectangle: -492.3,-935.54 -117.3,-810.54
  lines w7: -617.3,-810.54 382.7,-810.54 ; -617.3,-685.54 -617.3,-935.54 382.7,-935.54 382.7,-685.54 ; -492.3,-935.54 -492.3,-685.54 ; -367.3,-935.54 -367.3,-685.54 ; -117.3,-935.54 -117.3,-685.54 ; 132.7,-935.54 132.7,-685.54
  lines w10: -617.3,-1000.54 -617.3,-980.54 ; -557.3,-1010.54 -617.3,-990.54 ; -557.3,-970.54 -617.3,-990.54 ; -393.21,-990.54 -617.3,-990.54 ; 158.62,-990.54 382.7,-990.54 ; 322.7,-1010.54 382.7,-990.54 ; 322.7,-970.54 382.7,-990.54 ; 382.7,-1000.54 382.7,-980.54
  text "1000 (mil)" at -383.21,-1026.53 h60
M3 3D STEP Top:
  text ".Layer_Name" at -39.8,-1383.54 h60
M4 3D STEP Bottom:
  text ".Layer_Name" at -39.8,-1383.54 h60
M5 Assembly Top:
  circle w10: c380,1005 r10
  circle w10: c2415,705 r10
  circle w10: c1660,700 r10
  circle w10: c905,700 r10
  lines w10: -908.8,-1455.21 5691.2,-1455.21 ; -908.8,-1251.88 5693.2,-1251.88 ; -908.8,-1048.54 -908.8,-1658.54 3096.2,-1658.54 5693.2,-1658.54 5693.2,-1048.54 -908.3,-1048.54 -908.3,-1658.54 667.2,-1658.54 ; 1556.2,-1658.54 1556.2,-1048.54 ; 3131.2,-1251.88 3131.2,-1048.54 ; 3663.2,-1251.88 3663.2,-1048.54 ; 4285.2,-1665.04 4285.2,-1462.21
  text "COMPONENTS MARKED 'DNP' SHOULD NOT BE POPULATED." at 536.7,-843.54 h30
  text "ASSEMBLY VARIANT:" at 536.2,-959.04 h30
  text ".VariantName" at 1572.2,-959.04 h30
  text ".prj_number" at 2093.2,-1180.04 h30
  text "REV:" at 3178.2,-1180.04 h30
  text "PCB VIEWED FROM TOP SIDE" at -845.3,-1180.71 h30
  text "BOARD #:" at 1631.2,-1180.71 h30
  text "SVN REV:" at 3859.2,-1180.71 h30
  text ".VersionControl_RevNumber" at 4365.2,-1180.71 h30
  text "E1" at 3421.2,-1182.04 h30
  text ".prj_number" at 2083.2,-1370.04 h30
  text "TID #:" at 1621.2,-1370.71 h30
  text "Top Assembly" at -41.8,-1382.04 h30
  text "Layer name =" at -846.8,-1383.04 h30
  text "PLOT NAME =" at -845.3,-1589.38 h30
  text ".plot_File_Name" at -39.8,-1589.38 h30
  text "GENERATED    :" at 1633.2,-1589.38 h30
  text ".Print_Date" at 2502.7,-1589.38 h30
  text ".Print_Time" at 3231.7,-1589.38 h30
  text "TEXAS INSTRUMENTS" at 4496.2,-1589.38 h30
M6 Assembly Bottom:
  lines w10: -909.3,-1252.38 5692.7,-1252.38 ; -907.3,-1455.71 5692.7,-1455.71 ; 498.7,-1665.54 498.7,-1462.71 ; 1120.7,-1252.38 1120.7,-1049.04 ; 1557.2,-1251.88 1557.2,-1048.54 ; 3227.7,-1659.04 3227.7,-1049.04 ; 4116.7,-1659.04 5692.2,-1659.04 5692.2,-1049.04 -909.3,-1049.04 -909.3,-1659.04 1687.7,-1659.04 5692.7,-1659.04 5692.7,-1049.04
  text "COMPONENTS MARKED 'DNP' SHOULD NOT BE POPULATED." at 5485.2,-843.04 h30
  text ".VariantName" at 4441.2,-959.04 h30
  text "ASSEMBLY VARIANT:" at 5480.2,-959.04 h30
  text "REV:" at 1494.2,-1177.04 h30
  text ".VersionControl_RevNumber" at 418.7,-1181.21 h30
  text "SVN REV:" at 924.7,-1181.21 h30
  text "TIDA-00753" at 2607.2,-1181.21 h30
  text "BOARD #:" at 3152.7,-1181.21 h30
  text "PCB VIEWED FROM BOTTOM SIDE" at 5629.2,-1181.21 h30
  text "E1" at 1270.2,-1184.04 h30
  text "Bottom Assembly" at 4820,-1365 h30
  text "TID #:" at 3152.7,-1371.21 h30
  text "Layer Name :" at 5630,-1375 h30
  text "TIDA-00753" at 2607.2,-1376.21 h30
  text "TEXAS INSTRUMENTS" at 287.7,-1589.88 h30
  text ".Print_Time" at 1552.2,-1589.88 h30
  text ".Print_Date" at 2281.2,-1589.88 h30
  text "GENERATED    :" at 3150.7,-1589.88 h30
  text ".plot_File_Name" at 4823.7,-1589.88 h30
  text "PLOT NAME =" at 5629.2,-1589.88 h30
M9 Title Sheet:
  drawing of 57 lines, arcs and shapes, not listed
  text "1" at 123.04,7511.46 h70
  text "2" at 2618.7,7511.46 h70
  text "3" at 5108.05,7511.46 h70
  text "4" at 7614.71,7511.46 h70
  text "5" at 10113.7,7511.46 h70
  text "6" at 12618.7,7511.46 h70
  text "A" at -1033.3,6368.46 h70
  text "A" at 13766.7,6368.46 h70
  text "B" at -1033.3,3988.46 h70
  text "B" at 13766.7,3988.46 h70
  text "C" at -1033.3,1613.46 h70
  text "C" at 13766.7,1613.46 h70
  text "PROJECT TITLE:" at 10726.7,-247.54 h45
  text "TIDA-00753" at 10776.7,-380.87 h70
  text "DESIGNED FOR:" at 10726.7,-548.54 h45
  text ".PRJ_Customer" at 10776.7,-688.54 h70
  text "D" at -1033.3,-756.54 h70
  text "D" at 13766.7,-756.54 h70
  text "FILE NAME:" at 10726.7,-848.54 h45
  text "TIDA-00753" at 11081.2,-954.04 h70
  text "Texas Instruments (TI) and/or its licensors do not warrant the accuracy or completeness of this specification" at 5757.2,-1130.38 h45
  text "ENGINEER:" at 10726.7,-1138.54 h45
  text "LAYOUT BY:" at 12231.7,-1138.54 h45
  text "or any information contained therein. TI and/or its licensors do not warrant that this design will meet" at 5712.22,-1243.05 h45
  text ".PRJ_Engineer" at 10776.7,-1293.54 h70
  text ".PCB_Layout" at 12282.2,-1293.54 h40
  text "the specifications, will be suitable for your application or fit for any particular purpose, or will operate in" at 5712.22,-1355.71 h45
  text "ALTIUM DESIGNER VERSION:" at 12231.7,-1448.54 h45
  text "an implementation. TI and/or its licensors do not warrant that the design is production worthy. You should" at 5712.22,-1468.38 h45
  text "completely validate and test your design implementation to confirm the system functionality for your application." at 5757.2,-1581.04 h45
  text ".print_Scale" at 10776.7,-1581.87 h70
  text ".Application_BuildNumber" at 12282.2,-1581.87 h70
  text "1" at 123.04,-1788.54 h70
  text "2" at 2618.7,-1788.54 h70
  text "3" at 5108.05,-1788.54 h70
  text "4" at 7614.71,-1788.54 h70
  text "5" at 10113.7,-1788.54 h70
  text "6" at 12618.7,-1788.54 h70
M10 Fab Notes:
  drawing of 212 lines, arcs and shapes, not listed
  text "DESIGN INFORMATION" at 11764.22,6284.96 h60
  text "(REFER ALSO ARRAY/PANEL PROFILING INFORMATION)" at 11402.66,6123.24 h60
  text "BOARD SIZE" at 10716.66,6118.96 h60
  text "80 MM" at 11178.98,5991.13 h60
  text "X" at 11684.66,5991.13 h60
  text "50 MM" at 11915.98,5991.13 h60
  text "Number of Layers :" at 11114.66,5890.96 h60
  text "2" at 12209.47,5880.96 h60
  text "MIN. TRACK WIDTH:" at 11114.66,5751.96 h60
  text "10" at 12210.9,5751.96 h60
  text "MIL" at 12365.66,5751.96 h60
  text "8" at 12225,5625 h60
  text "MIL" at 12350,5625 h60
  text "MIN. CLEARANCE:" at 11114.66,5619.96 h60
  text "MIN. VIA PAD SIZE:" at 11114.66,5487.96 h60
  text "MIL" at 12365.66,5487.96 h60
  text "32" at 12175,5485 h60
  text "5.91MIL (0.150mm)" at 11809.66,5346.24 h60
  text "MINIMUM ANNULAR RING" at 10785.43,5341.96 h60
  text "EXTERNAL" at 12653.2,5341.96 h60
  text "PER" at 10985.43,5223.96 h60
  text "IPC-D-275 CLASS 2 LEVEL C" at 11205.43,5223.96 h60
  text "MIL, HOLES" at 12693.66,5111.67 h60
  text "+/-" at 12301.2,5110.96 h60
  text "+/-" at 13155.2,5110.96 h60
  text "REGISTRATION TOLERANCES:" at 10785.43,5105.96 h60
  text "METAL" at 11985.2,5105.96 h60
  text "5" at 12561.4,5105.96 h60
  text "3" at 13394.4,5105.96 h60
  text "MIL" at 13510.66,5105.96 h60
  text "ITS NOT AN IMPENDANCE CONTROL BOARD" at 11017.66,4988.96 h60
  text "MATERIAL:" at 10715.66,4799.5 h60
  text "FR-4 High Tg" at 11702.1,4659.16 h60
  text "FR-408" at 11136.66,4650.59 h60
  text "X" at 11548.66,4650.59 h60
  text "OTHER" at 12624.66,4650.59 h60
  text "63 MIL (1.6mm) +/-10%" at 11456.76,4487.88 h60
  text "THICKNESS:" at 10790.43,4483.59 h60
  text "X" at 11328.6,4483.59 h60
  text "OTHER" at 12741.66,4483.59 h60
  text "TOLERANCE:" at 10790.43,4325.59 h60
  text "X" at 11629.74,4325.59 h60
  text "ANSI IPC-6012 TYPE 3 CLASS 2" at 11816.68,4325.59 h60
  text "OTHER +/-" at 11816.66,4169.59 h60
  text "BOW & TWIST:" at 10790.43,4012.59 h60
  text "X" at 11629.74,4012.59 h60
  text "ANSI IPC-6012 TYPE 3 CLASS 2" at 11816.68,4012.59 h60
  text "OTHER +/-" at 11816.66,3854.09 h60
  text "COPPER THICKNESS (FINISHED):" at 10715.66,3718.59 h60
  text "1.4MIL (1oz)" at 11595.66,3565.88 h60
  text "2MIL (1.4oz)" at 12362.66,3565.88 h60
  text "2.8MIL (2oz)" at 13089.66,3565.88 h60
  text "OUTER:" at 11072.66,3561.59 h60
  text "X" at 11467.2,3560.96 h60
  text "1.4MIL (1oz)" at 11595.66,3408.88 h60
  text "2.8MIL (2oz)" at 12362.66,3408.88 h60
  text "N/A" at 13089.2,3409.24 h60
  text "INNER SIGNAL:" at 10783.58,3404.59 h60
  text "DRILLING:" at 10715.66,3265.59 h60
  text "REFERENCE:" at 10790.43,3148.59 h60
  text "X" at 11438.66,3148.59 h60
  text "AS SHOWN" at 11625.66,3148.59 h60
  text "X" at 12339.66,3148.59 h60
  text "NC_DRILL FILES" at 12476.66,3148.59 h60
  text "PTH MIN COPPER THICKNESS:" at 10790.43,2990.59 h60
  text "X" at 12140.66,2990.59 h60
  text "1MIL" at 12277.66,2990.59 h60
  text "OTHER" at 12774.66,2990.59 h60
  text "BOARD FINISH:" at 10715.66,2831.59 h60
  text "SILKSCREEN:" at 10870.88,2713.59 h60
  text "X" at 11819.66,2713.59 h60
  text "TOP" at 11945.66,2713.59 h60
  text "X" at 12329.66,2713.59 h60
  text "BOTTOM" at 12456.66,2713.59 h60
  text "SILKSCREEN COLOR:" at 10870.88,2546.59 h60
  text "X" at 11818.62,2546.59 h60
  text "WHITE" at 11945.66,2546.59 h60
  text "OTHER" at 12456.66,2546.59 h60
  text "SOLDER RESIST COLOR:" at 10870.88,2376.59 h60
  text "X" at 11438.62,2217.4 h60
  text "GREEN" at 11565.66,2217.4 h60
  text "BLUE" at 12156.66,2217.4 h60
  text "OTHER" at 12694.66,2217.4 h60
  text "IMMERSION GOLD (ENIG)" at 11776.66,2028.88 h60
  text "ENEPIG" at 13114.2,2025.59 h60
  text "SURFACE FINISH:" at 10715.66,2024.59 h60
  text "X" at 11589.72,2024.59 h60
  text "IMM. TIN/SILVER OR EQUIV" at 11045.2,1867.59 h60
  text "OTHER" at 12476.66,1867.59 h60
  text "ARRAY/PANEL:" at 10715.66,1688.59 h60
  text "CUT AND TRIM PER MECH LAYER 1" at 11776.66,1684.31 h60
  text "N.C. ROUTE" at 11776.66,1532.59 h60
  text "X" at 12455.66,1532.59 h60
  text "V. SCORE" at 12642.66,1532.59 h60
  text "CERTIFICATION:" at 10715.66,1395.59 h60
  text "MATERIALS AND WORKMANSHIP FOR ALL PCBS" at 11440.66,1395.59 h60
  text "TO MEET OR EXCEED THE REQUIREMENTS OF:" at 11440.66,1297.59 h60
  text "X" at 11067.17,1161.09 h60
  text "ANSI IPC-A-600F CLASS ->" at 11206.16,1161.09 h60
  text "X" at 12845.22,1161.09 h60
  text "2" at 12964.16,1161.09 h60
  text "1" at 12649.17,1159.59 h60
  text "3" at 13318.16,1159.59 h60
  text "X" at 11069.22,1001.59 h60
  text "UL 94V-0" at 11206.17,1001.59 h60
  text "X" at 11881.22,1001.59 h60
  text "RoHS" at 12018.17,1001.59 h60
  text "OTHER" at 12662.57,1001.59 h60
  text "PER ORDER" at 13059.62,1001.59 h60
  text "ADDITIONAL REQUIREMENTS:" at 10715.66,860.59 h60
  text "MICROSECTION:" at 10790.43,745.59 h60
  text "YES" at 11696.16,745.59 h60
  text "REQUIRED" at 12557.66,589.45 h60
  text "BARE BOARD ELEC. TEST:" at 10790.43,586.59 h60
  text "NONE" at 12096.16,586.59 h60
  text "X" at 12430.66,586.59 h60
  text "PER ORDER" at 13149.66,586.59 h60
  text "MANUFACTURER'S UL:" at 10790.43,429.59 h60
  text "RAIL" at 11956.16,425.31 h60
  text "METAL" at 12447.98,425.31 h60
  text "X" at 12823.2,424.96 h60
  text "SILK" at 12959.66,425.31 h60
M11 Gerber Information:
  lines w10: -908.8,-1455.21 5691.2,-1455.21 ; -908.8,-1251.88 5693.2,-1251.88 ; -908.8,-1048.54 -908.8,-1658.54 3096.2,-1658.54 5693.2,-1658.54 5693.2,-1048.54 ; -908.3,-1055.04 5693.2,-1055.04 ; -908.3,-1048.54 -908.3,-1658.54 667.2,-1658.54 ; 1556.2,-1658.54 1556.2,-1048.54 ; 3128.2,-1253.38 3128.2,-1050.04 ; 3663.2,-1251.88 3663.2,-1048.54 ; 4285.2,-1665.04 4285.2,-1462.21
  text "REV:" at 3178.2,-1179.04 h60
  text "TIDA-00753" at 2093.2,-1180.04 h60
  text "ALL ARTWORK VIEWED FROM TOP SIDE" at -845.3,-1180.71 h60
  text "BOARD #:" at 1631.2,-1180.71 h60
  text "SVN REV:" at 3859.2,-1180.71 h60
  text ".VersionControl_RevNumber" at 4365.2,-1180.71 h60
  text "E1" at 3423.2,-1184.04 h60
  text "LAYER NAME =" at -845.3,-1383.54 h60
  text "TID #: TIDA-00753" at 1638.2,-1385.04 h60
  text "PLOT NAME =" at -845.3,-1589.38 h60
  text ".plot_File_Name" at -39.8,-1589.38 h60
  text "GENERATED    :" at 1633.2,-1589.38 h60
  text ".Print_Date" at 2502.7,-1589.38 h60
  text ".Print_Time" at 3231.7,-1589.38 h60
  text "TEXAS INSTRUMENTS" at 4496.2,-1589.38 h60
M12 Stackup:
  lines w6: 10743.2,6934.96 13293.2,6934.96 ; 10743.2,7039.36 13293.2,7039.36 ; 10683.2,6449.96 ccw(c10717.2,6449.96) 10717.2,6415.96 13319.2,6415.96 ccw(c13319.2,6449.96) 13353.2,6449.96 13353.2,7155.96 ccw(c13319.2,7155.96) 13319.2,7189.96 10717.2,7189.96 ccw(c10717.2,7155.96) 10683.2,7155.96 10683.2,6449.96
  text "Layer Stack Up Detail for: TIDA-00753_V2_E1.PcbDoc" at 10743.2,7072.06 h40
  text "Layer" at 10743.2,7000.36 h30
  text "Gerber" at 11639.02,7000.36 h30
  text "Copper" at 12202.53,7000.36 h30
  text "Dielectric" at 12805.24,7000.36 h30
  text "Name" at 10743.2,6952.36 h30
  text "Document" at 11639.02,6952.36 h30
  text "Thickness" at 12202.53,6952.36 h30
  text "Material" at 12805.24,6952.36 h30
  text "Top Solder Mask" at 10743.2,6859.39 h34
  text "(.GTS)" at 11639.02,6859.39 h34
  text "Solder Resist" at 12805.24,6859.39 h34
  text "FR-4 High Tg" at 12805.24,6779.27 h34
  text "Top Layer" at 10743.2,6762.64 h34
  text "(.GTL)" at 11639.02,6762.64 h34
  text "1.4mil" at 12202.53,6762.64 h34
  text "FR-4 High Tg" at 12798.2,6666.96 h34
  text "Bottom Layer" at 10743.2,6665.89 h34
  text "(.GBL)" at 11639.02,6665.89 h34
  text "1.4mil" at 12202.53,6665.89 h34
  text "Bottom Solder Mask" at 10743.2,6569.14 h34
  text "(.GBS)" at 11639.02,6569.14 h34
  text "Solder Resist" at 12805.24,6569.14 h34
M13 Component Bodies Top:
  text ".Layer_Name" at -39.8,-1383.54 h60
  text ".Layer_Name" at -39.8,-1383.54 h60
M14 Component Bodies Bottom:
  text ".Layer_Name" at -39.8,-1383.54 h60
M15 Courtyards Top:
  text ".Layer_Name" at -39.8,-1383.54 h60
M16 Courtyards Bottom:
  text ".Layer_Name" at -39.8,-1383.54 h60
Drill Drawing:
  text ".legend" at 331.2,3040.96 h60
  text "Drill Table" at 331.2,2865.96 h60
  text "FOR 16MIL DRILL +0/-16MIL" at 340,2745 h60
  text "FOR PTH DRILL +/-3MIL" at 340,2670 h60
  text ".Layer_Name" at -39.8,-1383.54 h60

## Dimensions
0,0 to 3149.61,0 on M2 Board Dimensions
3149.61,0 to 3149.61,1968.5 on M2 Board Dimensions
